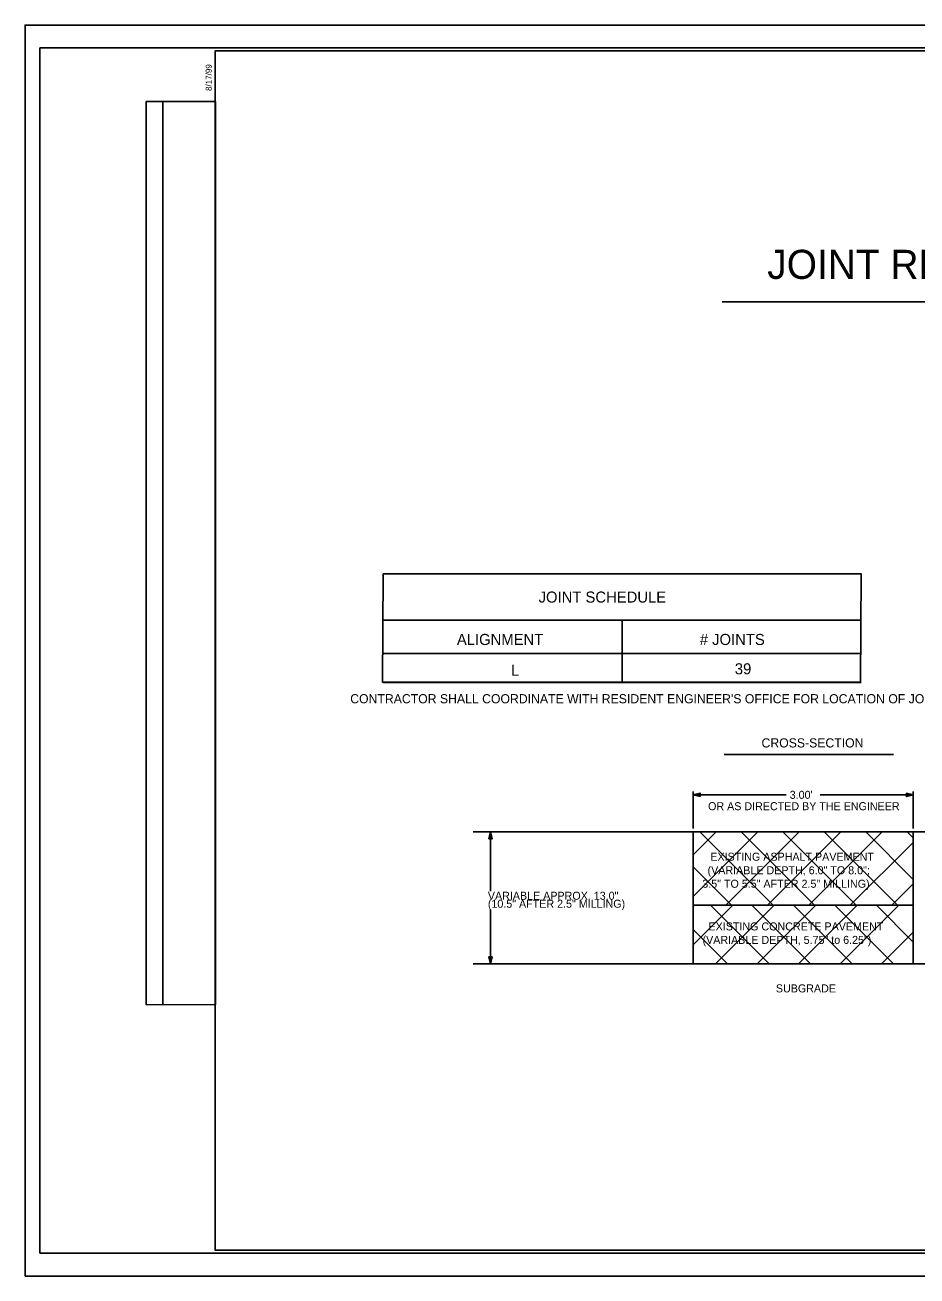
# Model space of a CAD drawing. Extents: x 2455709 to 2456046, y 594728 to 594947.
# Drawn here: x 2455708.8 to 2455864.9, y 594727.6 to 594946.6 of the extents above; entities that cross this region are included whole.
import ezdxf

# ---------------------------------------------------------------- set-up
doc = ezdxf.new("R2010")
doc.units = 0
for name, color, linetype in [('Default', 7, 'Continuous'), ('Old_Level_3', 7, 'Continuous'), ('Prop Horizontal Alignment', 7, 'Continuous'), ('Prop Roadway Culvert', 7, 'Continuous'), ('Prop Vertical Profile Grade', 7, 'Continuous'), ('Scratch_Level_3', 7, 'Continuous')]:
    doc.layers.add(name, color=color, linetype=linetype)

msp = doc.modelspace()

# ---------------------------------------------------------------- linework, layer by layer
at = {"layer": 'Default'}
for p, q in [((2455830.77, 594898.13), (2455928.67, 594898.13)), ((2455830.77, 594898.13), (2455928.67, 594898.13)), ((2455771.47, 594842.38), (2455855.11, 594842.38)), ((2455771.47, 594842.38), (2455855.11, 594842.38)), ((2455813.29, 594831.47), (2455813.29, 594842.38)), ((2455813.29, 594831.47), (2455813.29, 594842.38)), ((2455771.47, 594836.54), (2455855.11, 594836.54)), ((2455771.47, 594836.54), (2455855.11, 594836.54)), ((2455771.47, 594831.47), (2455855.11, 594831.47)), ((2455771.47, 594831.47), (2455855.11, 594831.47)), ((2455831.14, 594818.89), (2455860.76, 594818.89)), ((2455831.14, 594818.89), (2455860.76, 594818.89)), ((2455825.71, 594805.92), (2455825.71, 594812.41)), ((2455825.71, 594805.92), (2455825.71, 594812.41)), ((2455841.99, 594811.81), (2455825.71, 594811.81)), ((2455841.99, 594811.81), (2455825.71, 594811.81)), ((2455847.92, 594811.81), (2455864.2, 594811.81)), ((2455847.92, 594811.81), (2455864.2, 594811.81)), ((2455864.2, 594805.92), (2455864.2, 594812.41)), ((2455864.2, 594805.92), (2455864.2, 594812.41)), ((2455787.22, 594805.32), (2455825.71, 594805.32)), ((2455787.22, 594805.32), (2455825.71, 594805.32)), ((2455787.82, 594805.32), (2455790.84, 594805.32)), ((2455787.82, 594805.32), (2455790.84, 594805.32)), ((2455790.24, 594794.97), (2455790.24, 594805.32)), ((2455790.24, 594794.97), (2455790.24, 594805.32)), ((2455825.71, 594782.22), (2455825.71, 594805.32)), ((2455825.71, 594805.32), (2455864.2, 594805.32)), ((2455825.71, 594801.29), (2455829.73, 594805.32)), ((2455825.71, 594794.03), (2455836.99, 594805.32)), ((2455825.71, 594782.22), (2455825.71, 594805.32)), ((2455825.71, 594805.32), (2455864.2, 594805.32)), ((2455825.71, 594801.29), (2455829.73, 594805.32)), ((2455825.71, 594794.03), (2455836.99, 594805.32)), ((2455826.85, 594805.32), (2455839.69, 594792.49)), ((2455826.85, 594805.32), (2455839.69, 594792.49)), ((2455831.42, 594792.49), (2455844.25, 594805.32)), ((2455831.42, 594792.49), (2455844.25, 594805.32)), ((2455834.11, 594805.32), (2455846.94, 594792.49)), ((2455834.11, 594805.32), (2455846.94, 594792.49)), ((2455838.68, 594792.49), (2455851.51, 594805.32)), ((2455838.68, 594792.49), (2455851.51, 594805.32)), ((2455841.37, 594805.32), (2455854.2, 594792.49)), ((2455841.37, 594805.32), (2455854.2, 594792.49)), ((2455845.93, 594792.49), (2455858.76, 594805.32)), ((2455845.93, 594792.49), (2455858.76, 594805.32)), ((2455848.63, 594805.32), (2455861.46, 594792.49)), ((2455848.63, 594805.32), (2455861.46, 594792.49)), ((2455855.89, 594805.32), (2455864.2, 594797)), ((2455855.89, 594805.32), (2455864.2, 594797)), ((2455863.14, 594805.32), (2455864.2, 594804.26)), ((2455863.14, 594805.32), (2455864.2, 594804.26)), ((2455864.2, 594805.32), (2455902.69, 594805.32)), ((2455864.2, 594782.22), (2455864.2, 594805.32)), ((2455864.2, 594805.32), (2455902.69, 594805.32)), ((2455864.2, 594782.22), (2455864.2, 594805.32)), ((2455853.19, 594792.49), (2455864.2, 594803.49)), ((2455853.19, 594792.49), (2455864.2, 594803.49)), ((2455825.71, 594799.2), (2455832.43, 594792.49)), ((2455825.71, 594799.2), (2455832.43, 594792.49)), ((2455860.45, 594792.49), (2455864.2, 594796.24)), ((2455860.45, 594792.49), (2455864.2, 594796.24)), ((2455790.24, 594791.72), (2455790.24, 594782.22)), ((2455825.71, 594792.49), (2455864.2, 594792.49)), ((2455825.71, 594785.57), (2455832.63, 594792.49)), ((2455825.71, 594792.49), (2455864.2, 594792.49)), ((2455825.71, 594785.57), (2455832.63, 594792.49)), ((2455828.73, 594792.49), (2455838.99, 594782.22)), ((2455828.73, 594792.49), (2455838.99, 594782.22)), ((2455829.62, 594782.22), (2455839.88, 594792.49)), ((2455829.62, 594782.22), (2455839.88, 594792.49)), ((2455835.98, 594792.49), (2455846.25, 594782.22)), ((2455835.98, 594792.49), (2455846.25, 594782.22)), ((2455836.88, 594782.22), (2455847.14, 594792.49)), ((2455836.88, 594782.22), (2455847.14, 594792.49)), ((2455843.24, 594792.49), (2455853.51, 594782.22)), ((2455843.24, 594792.49), (2455853.51, 594782.22)), ((2455844.13, 594782.22), (2455854.4, 594792.49)), ((2455844.13, 594782.22), (2455854.4, 594792.49)), ((2455850.5, 594792.49), (2455860.76, 594782.22)), ((2455850.5, 594792.49), (2455860.76, 594782.22)), ((2455851.39, 594782.22), (2455861.66, 594792.49)), ((2455851.39, 594782.22), (2455861.66, 594792.49)), ((2455857.76, 594792.49), (2455864.2, 594786.04)), ((2455857.76, 594792.49), (2455864.2, 594786.04)), ((2455825.71, 594788.25), (2455831.73, 594782.22)), ((2455825.71, 594788.25), (2455831.73, 594782.22)), ((2455858.65, 594782.22), (2455864.2, 594787.77)), ((2455858.65, 594782.22), (2455864.2, 594787.77)), ((2455787.22, 594782.22), (2455825.71, 594782.22)), ((2455787.22, 594782.22), (2455825.71, 594782.22)), ((2455787.82, 594782.22), (2455790.84, 594782.22)), ((2455787.82, 594782.22), (2455790.84, 594782.22)), ((2455825.71, 594782.22), (2455864.2, 594782.22)), ((2455825.71, 594782.22), (2455864.2, 594782.22)), ((2455864.2, 594782.22), (2455902.69, 594782.22)), ((2455864.2, 594782.22), (2455902.69, 594782.22))]:
    msp.add_line(p, q, dxfattribs=at)
for points in [[(2455771.47, 594850.47), (2455855.11, 594850.47), (2455854.95, 594831.54), (2455771.32, 594831.54)], [(2455771.47, 594850.47), (2455855.11, 594850.47), (2455854.95, 594831.54), (2455771.32, 594831.54)], [(2455826.91, 594811.51), (2455825.71, 594811.81), (2455826.91, 594812.11)], [(2455826.91, 594811.51), (2455825.71, 594811.81), (2455826.91, 594812.11)], [(2455863, 594812.11), (2455864.2, 594811.81), (2455863, 594811.51)], [(2455863, 594812.11), (2455864.2, 594811.81), (2455863, 594811.51)], [(2455789.94, 594804.11), (2455790.24, 594805.32), (2455790.54, 594804.11)], [(2455789.94, 594804.11), (2455790.24, 594805.32), (2455790.54, 594804.11)], [(2455790.54, 594783.42), (2455790.24, 594782.22), (2455789.94, 594783.42)], [(2455790.54, 594783.42), (2455790.24, 594782.22), (2455789.94, 594783.42)]]:
    msp.add_lwpolyline(points, close=True, dxfattribs=at)
at = {"layer": 'Prop Horizontal Alignment'}
msp.add_line((2455742.1, 594942.08), (2455742.1, 594942.08), dxfattribs=at)
msp.add_lwpolyline([(2456042.11, 594942.08), (2455742.1, 594942.08), (2455742.1, 594732.08), (2456042.11, 594732.08)], close=True, dxfattribs=at)
at = {"layer": 'Prop Roadway Culvert'}
msp.add_lwpolyline([(2455708.81, 594727.57), (2456045.51, 594727.57), (2456045.51, 594946.57), (2455708.81, 594946.57)], close=True, dxfattribs=at)
at = {"layer": 'Prop Vertical Profile Grade'}
msp.add_lwpolyline([(2455711.41, 594731.57), (2456044.6, 594731.58), (2456044.61, 594942.57), (2455711.41, 594942.57)], close=True, dxfattribs=at)
at = {"layer": 'Scratch_Level_3'}
msp.add_line((2455732.91, 594775.08), (2455732.91, 594933.2), dxfattribs=at)
msp.add_lwpolyline([(2455730, 594775.07), (2455730, 594933.2), (2455742.11, 594933.21), (2455742.11, 594775.08)], close=True, dxfattribs=at)

# ---------------------------------------------------------------- texts
at = {"layer": 'Default'}
for s, height, p in [('JOINT SCHEDULE', 1.9372, (2455798.66, 594845.46)), ('JOINT SCHEDULE', 1.9372, (2455798.66, 594845.46)), ('ALIGNMENT', 1.937, (2455784.36, 594838.04)), ('# JOINTS', 1.937, (2455826.86, 594838.04)), ('# JOINTS', 1.937, (2455826.86, 594838.04)), ('39', 1.937, (2455832.99, 594832.9)), ('L', 1.94, (2455793.84, 594832.64)), ("CONTRACTOR SHALL COORDINATE WITH RESIDENT ENGINEER'S OFFICE FOR LOCATION OF JOINTS TO BE REPAIRED.", 1.601, (2455765.7, 594827.83)), ("CONTRACTOR SHALL COORDINATE WITH RESIDENT ENGINEER'S OFFICE FOR LOCATION OF JOINTS TO BE REPAIRED.", 1.601, (2455765.7, 594827.83)), ("3.00'", 1.401, (2455842.59, 594811.11)), ("3.00'", 1.401, (2455842.59, 594811.11)), ('OR AS DIRECTED BY THE ENGINEER', 1.4007, (2455828.31, 594809.12)), ('OR AS DIRECTED BY THE ENGINEER', 1.4007, (2455828.31, 594809.12)), ('EXISTING ASPHALT PAVEMENT', 1.4007, (2455828.7, 594800.27)), ('(VARIABLE DEPTH, 6.0" TO 8.0";', 1.4007, (2455828.22, 594797.9)), ('3.5" TO 5.5" AFTER 2.5" MILLING)', 1.4007, (2455827.3, 594795.54)), ('VARIABLE APPROX. 13.0" ', 1.4007, (2455789.78, 594793.44)), ('(10.5" AFTER 2.5" MILLING)', 1.4007, (2455789.78, 594792.04)), ('EXISTING CONCRETE PAVEMENT', 1.4007, (2455828.38, 594788.07)), ('(VARIABLE DEPTH, 5.75" to 6.25")', 1.4007, (2455827.34, 594785.71)), ('SUBGRADE', 1.401, (2455840.17, 594777.22)), ('SUBGRADE', 1.401, (2455840.17, 594777.22))]:
    msp.add_text(s, height=height, rotation=360, dxfattribs=at).set_placement(p)
at = {"layer": 'Old_Level_3'}
for s, height, p in [('JOINT REPAIR DETAIL', 5.0897, (2455838.66, 594902.13)), ('JOINT REPAIR DETAIL', 5.0897, (2455838.66, 594902.13)), ('CROSS-SECTION', 1.6008, (2455837.66, 594820.1)), ('CROSS-SECTION', 1.6008, (2455837.66, 594820.1))]:
    msp.add_text(s, height=height, rotation=0, dxfattribs=at).set_placement(p)
at = {"layer": 'Prop Horizontal Alignment'}
msp.add_text('8/17/99', height=1.05, rotation=90, dxfattribs=at).set_placement((2455741.46, 594935.03))

doc.saveas('drawing.dxf')
